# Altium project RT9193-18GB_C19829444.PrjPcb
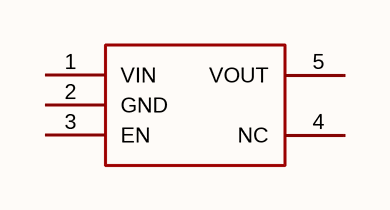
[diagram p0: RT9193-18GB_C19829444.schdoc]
1 sheet, 1 parts. Net scope: global (net labels, ports and power ports of the same name join across sheets).

## Sheet RT9193-18GB_C19829444.schdoc
size 127 x 101 mm

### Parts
U?  rt9193-18gb_c19829444  [SOT-23-5_L2.9-W1.6-P0.95-LS2.8-BR]  (value not drawn)

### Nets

Not connected (* = marked no-connect by the designer): U? 1(VIN) 2(GND) 3(EN) 4(NC) 5(VOUT)

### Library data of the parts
U? = rt9193-18gb_c19829444: 输出极性:正极;工作电压:6V;输出电压:1.8V;输出电流:300mA;电源纹波抑制比(PSRR):70dB@(1kHz);输出类型:固定;; Manufacturer: TECH PUBLIC(台舟); AddInBom: yes; ModelId: 7ba65df16e7b4570af156e925f9c37fe; ModelTransform: 114.173,114.173,0,90,0,0,0,0,0; Output Configuration: 正极; Voltage - Supply: 6V; Output Voltage: 1.8V; Output Current: 300mA; Voltage Dropout: 90mV@(100mA)；230mV@(200mA); standby current: 70uA; Noise: 50uVrms; Output Type: 固定; Number of Outputs: 1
